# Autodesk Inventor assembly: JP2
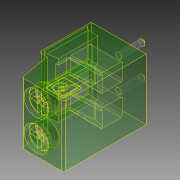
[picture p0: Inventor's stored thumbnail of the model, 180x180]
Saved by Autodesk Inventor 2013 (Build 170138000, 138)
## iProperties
Created: 2021-02
Part Number: JP2
Document SubType Name: Assembly
Designer: Fede
Author: Fede
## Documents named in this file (2)
- C:\0000 FEDE\16GB\0000 INTERIOR\DE_TMP_BAS\BAS_DTON - demora conexion al energizar\pcb\BOR\turn on\Imported Components\BAS_DTON\JP2.iam
- C:\0000 FEDE\16GB\0000 INTERIOR\DE_TMP_BAS\BAS_DTON - demora conexion al energizar\pcb\BOR\turn on\Imported Components\BAS_DTON\bornera2x1.iam
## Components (1 placed, 1 different names)
1. bornera2x1:1 [sub-assembly]
